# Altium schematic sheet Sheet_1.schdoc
size 305 x 189 mm
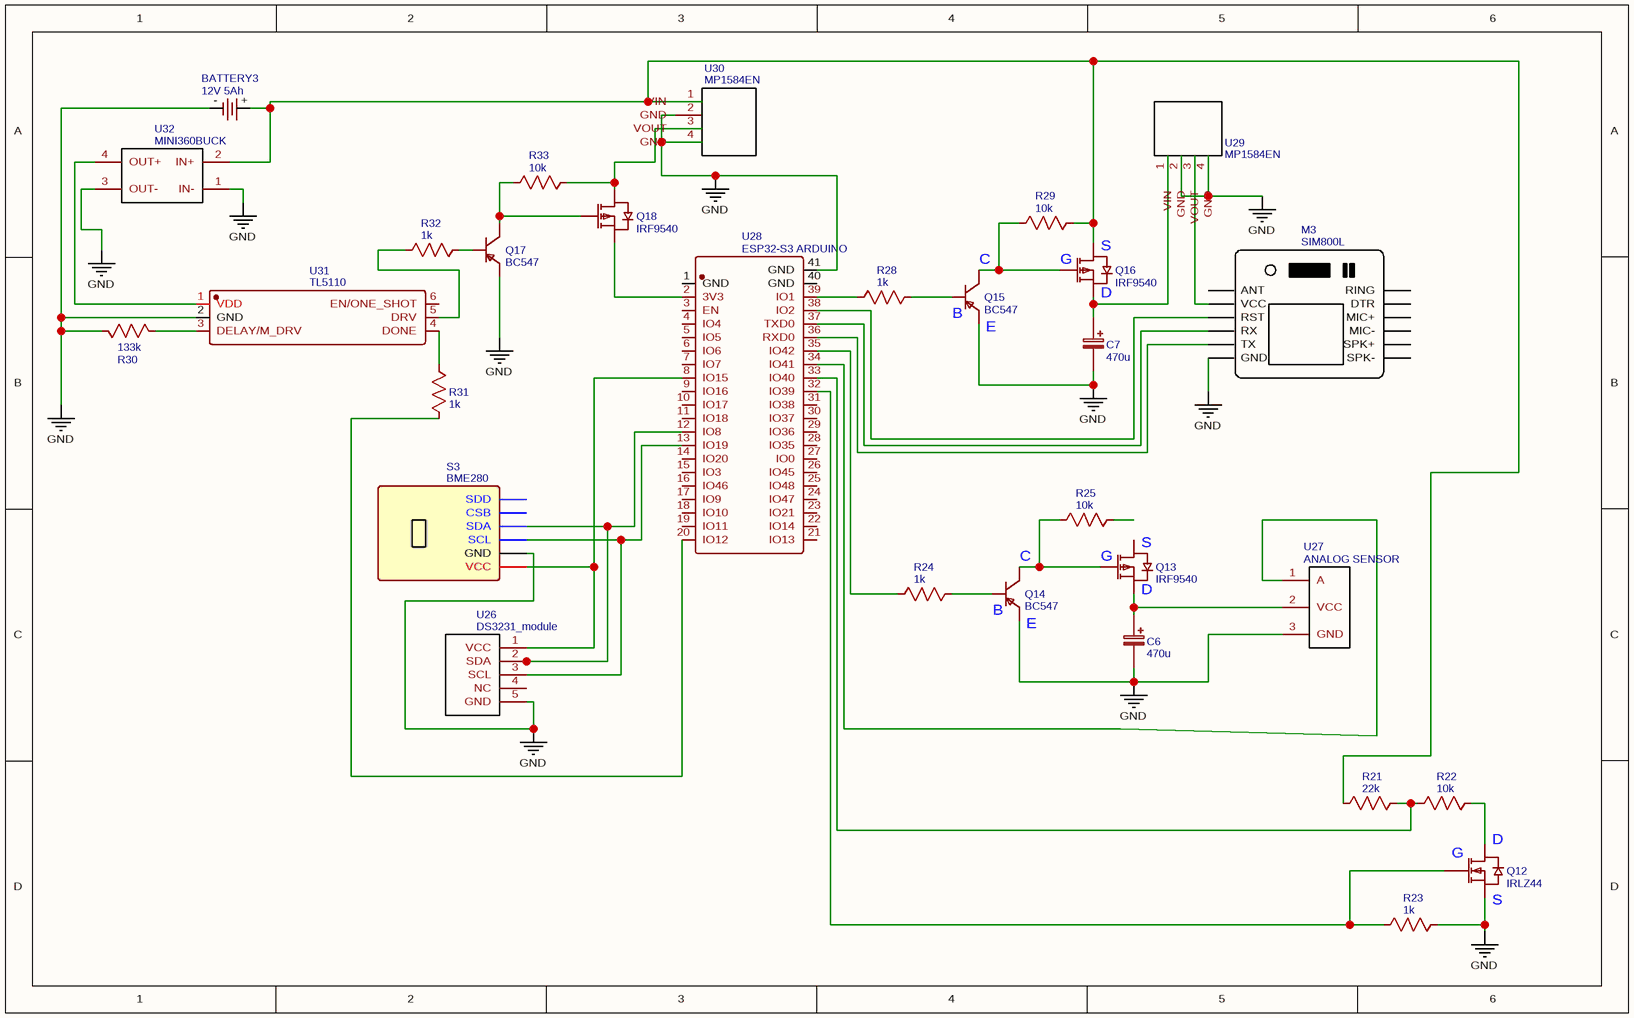
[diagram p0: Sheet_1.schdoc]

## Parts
BATTERY3  12V 5Ah  [BATTERY-SMD-MY-2032]
C6  470u  [CASE-A_3216]
C7  470u  [CASE-A_3216]
M3  SIM800L  [SIM800LMODULE_SIM800LMODULE]
Q12  IRLZ44  [TO-220-3_L10.0-W4.5-P2.54-T]
Q13  IRF9540  [TO-263-2_L10.0-W9.1-P5.08-LS15.2-BR]
Q14  BC547  [SOT-23-3_L2.9-W1.6-P1.90-LS2.8-TR-CW]
Q15  BC547  [SOT-23-3_L2.9-W1.6-P1.90-LS2.8-TR-CW]
Q16  IRF9540  [TO-263-2_L10.0-W9.1-P5.08-LS15.2-BR]
Q17  BC547  [SOT-23-3_L2.9-W1.6-P1.90-LS2.8-TR-CW]
Q18  IRF9540  [TO-263-2_L10.0-W9.1-P5.08-LS15.2-BR]
R21  22k  [R0603]
R22  10k  [R0603]
R23  1k  [R0603]
R24  1k  [R0603]
R25  10k  [R0603]
R28  1k  [R0603]
R29  10k  [R0603]
R30  133k  [R0603]
R31  1k  [R0603]
R32  1k  [R0603]
R33  10k  [R0603]
S3  BME280  [BME280]
U26  DS3231_module  [DS3231]
U27  ANALOG SENSOR  [ANALOG SENSOR V1]
U28  ESP32-S3 ARDUINO  [WIRELM-SMD_ESP32-S3-WROOM-1U]
U29  MP1584EN  [MP1584EN]
U30  MP1584EN  [MP1584EN]
U31  TL5110  [TSOT-23-6_L2.9-W1.6-P0.95-LS2.8-BR]
U32  MINI360BUCK  [MINI360BUCK]

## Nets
GND: BATTERY3.-(BAT-) C6.2 C7.2 M3.6(GND) Q12.3(S) Q14.1(E) Q15.1(E) Q17.1(E) R23.2 R30.1 S3.2(GND) U26.5(GND) U27.3(GND) U28.41(GND) U29.2(GND) U29.4(GND) U30.4(GND) U31.2(GND) U32.1(IN-) U32.3(OUT-)
NetBATTERY3_+: BATTERY3.+(BAT+) Q16.4(D) R21.1 R29.1 U30.1(VIN) U32.2(IN+)
NetC6_1: C6.1 Q13.3(S) U27.2(VCC)
NetC7_1: C7.1 Q16.3(S) U29.1(VIN)
NetM3_2: M3.2(VCC) U29.3(VOUT)
NetM3_3: M3.3(RST) U28.38(IO2)
NetM3_4: M3.4(RX) U28.37(TXD0)
NetM3_5: M3.5(TX) U28.36(RXD0)
NetQ12_1: Q12.1(G) R23.1 U28.32(IO39)
NetQ12_2: Q12.2(D) R22.2
NetQ13_1: Q13.1(G) Q14.3(C) R25.2
NetQ14_2: Q14.2(B) R24.2
NetQ15_2: Q15.2(B) R28.2
NetQ15_3: Q15.3(C) Q16.1(G) R29.2
NetQ17_2: Q17.2(B) R32.1
NetQ17_3: Q17.3(C) Q18.1(G) R33.2
NetQ18_3: Q18.3(S) U28.2(3V3)
NetQ18_4: Q18.4(D) R33.1 U30.3(VOUT)
NetR21_2: R21.2 R22.1 U28.33(IO40)
NetR24_1: R24.1 U28.35(IO42)
NetR28_1: R28.1 U28.39(IO1)
NetR30_2: R30.2 U31.3(DELAY/M_DRV)
NetR31_1: R31.1 U31.4(DONE)
NetR31_2: R31.2 U28.20(IO12)
NetR32_2: R32.2 U31.5(DRV)
NetS3_1: S3.1(VCC) U26.1(VCC) U28.8(IO15)
NetS3_3: S3.3(SCL) U26.3(SCL) U28.13(IO19)
NetS3_4: S3.4(SDA) U26.2(SDA) U28.12(IO8)
NetU27_1: U27.1(A) U28.34(IO41)
NetU31_1: U31.1(VDD) U32.4(OUT+)

Not connected (* = marked no-connect by the designer): M3 1(ANT) 7(SPK-) 8(SPK+) 9(MIC-) 10(MIC+) 11(DTR) 12(RING); Q13 4(D); R25 1; S3 5(CSB) 6(SDD); U26 4(NC); U28 1(GND) 3(EN) 4(IO4) 5(IO5) 6(IO6) 7(IO7) 9(IO16) 10(IO17) 11(IO18) 14(IO20) 15(IO3) 16(IO46) 17(IO9) 18(IO10) 19(IO11) 21(IO13) 22(IO14) 23(IO21) 24(IO47) 25(IO48) 26(IO45) 27(IO0) 28(IO35) 29(IO36) 30(IO37) 31(IO38) 40(GND); U30 2(GND); U31 6(EN/ONE_SHOT)

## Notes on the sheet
- (near Q15) C
- (near Q16) G
- (near Q16) S
- (near Q16) D
- (near Q15) B
- (near Q15) E
- (near Q14) C
- (near Q13) G
- (near Q13) S
- (near Q14) B
- (near Q14) E
- (near Q13) D
- (near Q12) G
- (near Q12) S
- (near Q12) D

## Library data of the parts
BATTERY3 = 12V 5Ah: Manufacturer: MYOUNG(美阳); Manufacturer Part: MY-2032-10; Contributor: lcsc
C6 C7 = 470u: nameAlias: Value(F); Contributor: LCEDA_Lib
M3 = SIM800L: Contributor: sharad.rask
Q12 = IRLZ44: Manufacturer: Infineon(英飞凌); Manufacturer Part: IRLZ44NPBF
Q13 Q16 Q18 = IRF9540: Manufacturer: IR; Manufacturer Part: IRF5210STRLPBF; Paste Type: expand; Contributor: LCEDA_Lib
Q14 Q15 Q17 = BC547: Manufacturer: KEC; Manufacturer Part: 2N3906S-RTK/PS; Contributor: LCEDA_Lib
R21 = 22k: nameAlias: Value(Ω); Contributor: LCEDA_Lib
R22 R25 R29 R33 = 10k: nameAlias: Value(Ω); Contributor: LCEDA_Lib
R23 R24 R28 R31 R32 = 1k: nameAlias: Value(Ω); Contributor: LCEDA_Lib
R30 = 133k: nameAlias: Value(Ω); Contributor: LCEDA_Lib
U26 = DS3231_module: Contributor: retret
U27 = ANALOG SENSOR: Contributor: utbahR
U28 = ESP32-S3 ARDUINO: Manufacturer: null; Manufacturer Part: ESP32-S3-WROOM-1U; Contributor: lcsc
U29 U30 = MP1584EN: Contributor: babeinlovexd
U31 = TL5110: Manufacturer: TI(德州仪器); Manufacturer Part: TPL5110DDCR; Contributor: lcsc; nameAlias: Value
U32 = MINI360BUCK: Contributor: Andrey Fedorov; sourceId: FRLFXR8qI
